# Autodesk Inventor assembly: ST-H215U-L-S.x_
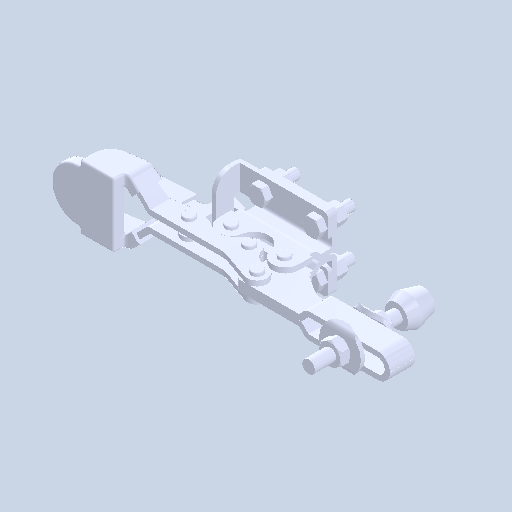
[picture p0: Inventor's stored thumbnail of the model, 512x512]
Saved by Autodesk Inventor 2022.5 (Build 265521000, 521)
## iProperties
Created: 2024-07
Part Number: ST-H215U-L-S.x_
Document SubType Name: Assembly
Designer: ImaoCorp
Author: ImaoCorp
Sending System: SOLIDWORKS 2022-2022290
MC: AMD64
MC_MODEL: Intel64 Family 6 Model 60 Stepping 3, GenuineIntel
OS: Windows_NT
FRU: Parasolid Version 33.1, build 260,  4-25-2022
FORMAT: text
GUISE: transmit
KEY: FILEST-H215U-L-S.x_t
DATE: Mon Jul 29 10:02:13 2024
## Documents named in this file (16)
- X:\14_SW2022-Inv2022\07_2024-10新製品(WHS)\OTC_データ\s\st-h215u-l-s\ST-H215U-L-S.x_.iam
- X:\14_SW2022-Inv2022\07_2024-10新製品(WHS)\OTC_データ\s\st-h215u-l-s\ST-H215U-L_01.ipt
- X:\14_SW2022-Inv2022\07_2024-10新製品(WHS)\OTC_データ\s\st-h215u-l-s\ST-H215U-L_02.ipt
- X:\14_SW2022-Inv2022\07_2024-10新製品(WHS)\OTC_データ\s\st-h215u-l-s\ST-H215U-L_03.ipt
- X:\14_SW2022-Inv2022\07_2024-10新製品(WHS)\OTC_データ\s\st-h215u-l-s\ST-H215U-L_04.ipt
- X:\14_SW2022-Inv2022\07_2024-10新製品(WHS)\OTC_データ\s\st-h215u-l-s\ST-H215U-L_05.ipt
- X:\14_SW2022-Inv2022\07_2024-10新製品(WHS)\OTC_データ\s\st-h215u-l-s\ST-H215U-L_06.ipt
- X:\14_SW2022-Inv2022\07_2024-10新製品(WHS)\OTC_データ\s\st-h215u-l-s\ST-H215U-L_07.ipt
- X:\14_SW2022-Inv2022\07_2024-10新製品(WHS)\OTC_データ\s\st-h215u-l-s\ST-H215U-L_08.ipt
- X:\14_SW2022-Inv2022\07_2024-10新製品(WHS)\OTC_データ\s\st-h215u-l-s\ST-H215U-L_09.ipt
- X:\14_SW2022-Inv2022\07_2024-10新製品(WHS)\OTC_データ\s\st-h215u-l-s\ST-H215U-L_10.ipt
- X:\14_SW2022-Inv2022\07_2024-10新製品(WHS)\OTC_データ\s\st-h215u-l-s\ST-H215U-L_11.ipt
- X:\14_SW2022-Inv2022\07_2024-10新製品(WHS)\OTC_データ\s\st-h215u-l-s\ST-H215U-L_12.ipt
- X:\14_SW2022-Inv2022\07_2024-10新製品(WHS)\OTC_データ\s\st-h215u-l-s\ST-H215U-L_13.ipt
- X:\14_SW2022-Inv2022\07_2024-10新製品(WHS)\OTC_データ\s\st-h215u-l-s\ST-H215U-L_14.ipt
- X:\14_SW2022-Inv2022\07_2024-10新製品(WHS)\OTC_データ\s\st-h215u-l-s\ST-H215U-L_15.ipt
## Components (15 placed, 15 different names)
1. ST-H215U-L_01
2. ST-H215U-L_02
3. ST-H215U-L_03
4. ST-H215U-L_04
5. ST-H215U-L_05
6. ST-H215U-L_06
7. ST-H215U-L_07
8. ST-H215U-L_08
9. ST-H215U-L_09
10. ST-H215U-L_10
11. ST-H215U-L_11
12. ST-H215U-L_12
13. ST-H215U-L_13
14. ST-H215U-L_14
15. ST-H215U-L_15
